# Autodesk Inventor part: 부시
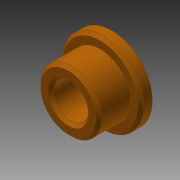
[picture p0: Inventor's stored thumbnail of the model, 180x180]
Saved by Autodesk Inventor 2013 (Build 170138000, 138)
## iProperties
Created: 2016-02
Part Number: 부시
Material: 강철, 연강
Document SubType Name: Modeling
Designer: test
Density: 1 g/cm^3
Author: test
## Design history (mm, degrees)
sketch "스케치1"
  geometry: C1 r 14 at (0, 0); C2 r 10.5 at (0, 0); 1 further point
  constraints: 2 centre point, 2 coincident
  dimensions: "d0" = 28 diameter of C1; "d1" = 21 diameter of C2
extrude "돌출1" new body sketch "스케치1" distance "d2" = 4; taper "d3" = 0 deg
extrude "돌출2" join sketch "스케치1" distance "d4" = 11; taper "d5" = 0 deg
hole "구멍1" diameter "d8" = 12; stored, may be unused: countersink angle "d12" = 90 deg, drill point angle "d14" = 118 deg; dims "d6" = 10, "d7" = 10, "d9" = 6, "d10" = 4, "d11" = 2, "d13" = 8
chamfer "모따기1" distance "d15" = 1; stored, may be unused: second distance "d16" = 2, angle "d17" = 45 deg
chamfer "모따기2" distance "d18" = 1; stored, may be unused: second distance "d19" = 2, angle "d20" = 45 deg
node "솔리드1"
